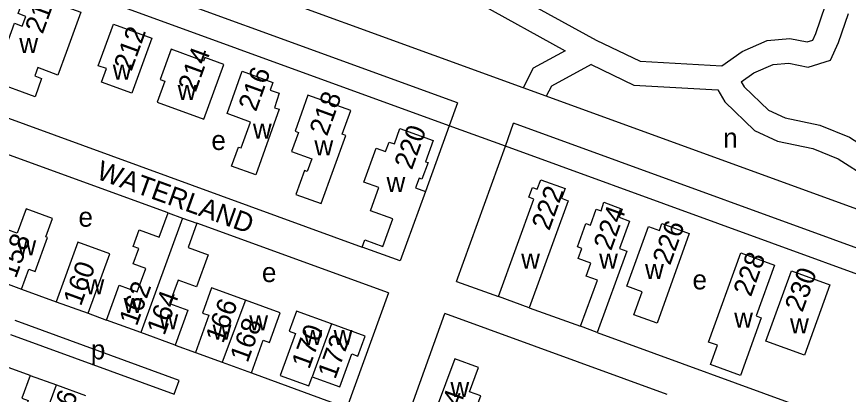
# Model space of a CAD drawing. Extents: x 154320 to 156262, y 382651 to 384180.
# Drawn here: x 155813.5 to 155984.2, y 382955.7 to 383033.1 of the extents above; entities that cross this region are included whole.
import ezdxf

# ---------------------------------------------------------------- set-up
doc = ezdxf.new("R2010")
doc.units = 0
for name, color, linetype in [('BLT_Basislijn', 7, 'Continuous'), ('BLT_Bebouwing', 7, 'Continuous'), ('BLT_Centroide', 7, 'Continuous'), ('BLT_Huisnummer', 7, 'Continuous'), ('BLT_Onderverdeling_panden', 7, 'Continuous'), ('BLT_Straatnaam', 7, 'Continuous'), ('BLT_Vlakafsluiter', 7, 'Continuous')]:
    doc.layers.add(name, color=color, linetype=linetype)

msp = doc.modelspace()

# ---------------------------------------------------------------- linework, layer by layer
at = {"layer": 'BLT_Basislijn'}
for p, q in [((155922.18, 383016.83), (155917.44, 383018.56)), ((156004.18, 382987.02), (155922.18, 383016.83)), ((155903.98, 383015.47), (155902.27, 383010.77)), ((155805.26, 383014.66), (155884.39, 382985.88)), ((155902.27, 383010.77), (155897.36, 382997.29)), ((155913.78, 383006.59), (155915.48, 383011.29)), ((155903.75, 382978.84), (155913.78, 383006.59)), ((155844.57, 382992.89), (155811.27, 383005.01)), ((155889.8, 382976.47), (155850.46, 382990.76)), ((155903.75, 382978.84), (155912.34, 382975.73)), ((155814.49, 382977.24), (155821.58, 382974.65)), ((155889.8, 382976.47), (155881.23, 382952.91)), ((155918.67, 382973.44), (155929.23, 382969.64)), ((155846.86, 382958.56), (155813.21, 382970.8)), ((155828.14, 382972.3), (155831.93, 382970.92)), ((155893.06, 382949.27), (155901.37, 382972.26)), ((155946.99, 382955.63), (155901.37, 382972.26)), ((155812.2, 382967.97), (155845.84, 382955.74)), ((155932.61, 382968.4), (155990.87, 382947.17)), ((155846.05, 382965.8), (155850.16, 382964.28)), ((155816.27, 382959.55), (155821.65, 382957.62)), ((155861.67, 382960.11), (155881.23, 382952.91))]:
    msp.add_line(p, q, dxfattribs=at)
for points in [[(155853.65, 383062.66), (155866.44, 383057.77), (155872.53, 383054.76), (155877.48, 383050.43), (155881.4, 383046.27), (155884.9, 383044.3), (155889.57, 383042.9), (155896.23, 383042.16), (155904.77, 383041.94), (155910.34, 383040.46), (155932.43, 383028.32)], [(155852.58, 383057.9), (155864.43, 383053.19), (155869.73, 383050.56), (155874.01, 383046.82), (155878.28, 383042.3), (155882.92, 383039.67), (155888.57, 383037.98), (155895.89, 383037.17), (155904.05, 383036.95), (155908.47, 383035.79), (155926.08, 383026.11), (155919.49, 383022.53), (155917.44, 383018.56)], [(155903.98, 383015.47), (155817.04, 383047.08)], [(155917.44, 383018.56), (155843.64, 383045.39)], [(155902.27, 383010.77), (155815.34, 383042.38)], [(155932.43, 383028.32), (155941.43, 383024.01), (155958.17, 383023.07), (155962.36, 383025.98), (155967.49, 383028.21), (155972.18, 383028.67), (155975.7, 383027.95), (155976.87, 383028.3), (155977.49, 383029.67), (155979.47, 383035.48)], [(155962.2, 383019.78), (155964.8, 383021.59), (155968.76, 383023.31), (155971.92, 383023.62), (155975.94, 383022.79), (155980.5, 383024.18), (155982.14, 383027.83), (155984.17, 383033.77)], [(155931.36, 383023.29), (155923.23, 383018.87), (155922.18, 383016.83)], [(155931.36, 383023.29), (155940.16, 383019.07), (155957.4, 383018.1)], [(155962.2, 383019.78), (155962.79, 383018.76), (155967.76, 383013.94), (155971.18, 383012.38), (155978.33, 383010.87), (155984.39, 383008.44), (155990.48, 383004.53), (155997.96, 383001.96), (156005.52, 383000.44), (156011.25, 382996.8)], [(155957.4, 383018.1), (155958.81, 383015.65), (155964.9, 383009.76), (155969.6, 383007.6), (155976.88, 383006.06), (155982.09, 383003.98), (155988.29, 383000), (155996.65, 382997.12), (156003.63, 382995.72), (156007.06, 382993.56), (156004.18, 382987.02)], [(156002.66, 382979.59), (155915.48, 383011.29)], [(156000.95, 382974.89), (155913.78, 383006.59)], [(155845.84, 382955.74), (155846.86, 382958.56)]]:
    msp.add_lwpolyline(points, dxfattribs=at)
at = {"layer": 'BLT_Bebouwing'}
for p, q in [((155844.57, 382992.89), (155847.5, 382991.83)), ((155847.5, 382991.83), (155850.46, 382990.76)), ((155808.04, 382979.61), (155814.49, 382977.24)), ((155918.67, 382973.44), (155912.34, 382975.73)), ((155932.61, 382968.4), (155929.23, 382969.64))]:
    msp.add_line(p, q, dxfattribs=at)
for points in [[(155815.34, 383038.14), (155826.66, 383034.03), (155823.68, 383025.81), (155821.96, 383021.11), (155817.81, 383022.67), (155817.2, 383020.97), (155818.61, 383020.47), (155817.26, 383016.69), (155808.67, 383019.81), (155813.04, 383031.76), (155814.64, 383031.16), (155815.37, 383033.18), (155813.77, 383033.75)], [(155833.36, 383031.61), (155841.21, 383028.73), (155837.13, 383017.47), (155830.92, 383019.72), (155831.93, 383022.47), (155830.25, 383023.07)], [(155845.22, 383026.44), (155842.97, 383020.26), (155843.91, 383019.91), (155842.33, 383015.58), (155851.91, 383012.09), (155856.01, 383023.32), (155852.1, 383024.76), (155851.84, 383024.03)], [(155859.79, 383021.94), (155866.04, 383019.63), (155865.51, 383018.04), (155867.38, 383017.42), (155866.4, 383014.46), (155867.37, 383014.13), (155862.54, 383000.7), (155857.58, 383002.49), (155858.99, 383006.4), (155859.58, 383006.2), (155861.49, 383011.5), (155856.68, 383013.25)], [(155873.27, 383017.02), (155870.64, 383009.65), (155871.33, 383009.4), (155869.9, 383005.47), (155874.04, 383003.97), (155873.11, 383001.38), (155872.54, 383001.58), (155870.78, 382996.66), (155875.99, 382994.8), (155881.02, 383008.75), (155880.31, 383009.04), (155882.06, 383013.88)], [(155945.91, 382990.69), (155951.5, 382988.68), (155944.91, 382970.29), (155940.17, 382972.02), (155941.88, 382976.71), (155938.69, 382977.88), (155943.14, 382990.07), (155945.39, 382989.25)], [(155962.08, 382984.71), (155969.04, 382982.18), (155965.25, 382971.77), (155966.3, 382971.39), (155962.01, 382959.57), (155955.85, 382961.82), (155957.3, 382965.75), (155955.46, 382966.42)], [(155972.47, 382980.98), (155980.39, 382978.13), (155975.16, 382963.7), (155967.26, 382966.56)]]:
    msp.add_lwpolyline(points, close=True, dxfattribs=at)
for points in [[(155884.73, 382999.21), (155887.29, 383006.19), (155889.21, 383005.48), (155889.92, 383007.42), (155891.01, 383007.03), (155892.13, 383010.16), (155898.98, 383007.7), (155897.41, 383003.39), (155897.94, 383003.2), (155896.66, 382999.78), (155896.07, 382999.98), (155895.34, 382998.02)], [(155912.34, 382975.73), (155919.61, 382995.73), (155918.59, 382996.11), (155919.34, 382998.13), (155920.34, 382997.76), (155921.04, 382999.65), (155926.04, 382997.87), (155925.32, 382995.88), (155926.68, 382995.39), (155918.67, 382973.44)], [(155884.39, 382985.88), (155884.93, 382987.37), (155888.61, 382986.03), (155890.66, 382991.65), (155886.07, 382993.31), (155886.85, 382995.46), (155887.81, 382998.11), (155884.73, 382999.21)], [(155895.34, 382998.02), (155897.36, 382997.29)], [(155897.36, 382997.29), (155892.19, 382983.05), (155884.39, 382985.88)], [(155929.23, 382969.64), (155932.68, 382979.09), (155930.38, 382979.95), (155931.29, 382982.61), (155928.75, 382983.53), (155929.5, 382985.6), (155928.56, 382985.93), (155930.28, 382990.72), (155931.28, 382990.36), (155932.43, 382993.64), (155933.42, 382993.28), (155933.99, 382995.06), (155937.76, 382993.68), (155937.14, 382991.99), (155939.23, 382991.22), (155937.17, 382985.57), (155938.68, 382985.02), (155932.61, 382968.4)], [(155814.49, 382977.24), (155815.98, 382981.38), (155817.31, 382980.89), (155819.85, 382987.84), (155819.48, 382987.97), (155820.85, 382991.73), (155815.41, 382993.72), (155813.59, 382988.73), (155811.62, 382989.45), (155808.04, 382979.61)], [(155831.93, 382970.92), (155834.53, 382978.05), (155838.25, 382976.69), (155840.02, 382981.51), (155837.39, 382982.47), (155838.54, 382985.6), (155837.42, 382986.01), (155838.66, 382989.39), (155842.76, 382987.92), (155844.57, 382992.89)], [(155850.46, 382990.76), (155848.67, 382985.78), (155852.77, 382984.3), (155850.38, 382977.75), (155846.62, 382979.12), (155844.88, 382974.31), (155848.64, 382972.95), (155846.05, 382965.8), (155846.05, 382965.8)], [(155828.14, 382972.3), (155832.59, 382984.5), (155826.01, 382986.88), (155821.58, 382974.65)], [(155860.45, 382974.97), (155853.47, 382977.5), (155851.64, 382972.35), (155852.91, 382971.89), (155850.16, 382964.28)], [(155821.58, 382974.65), (155828.14, 382972.3)], [(155861.67, 382960.11), (155864.1, 382966.79), (155865.39, 382966.35), (155867.58, 382972.37), (155860.45, 382974.97)], [(155878.07, 382970.16), (155870.91, 382972.76), (155869.43, 382968.64), (155870.72, 382968.18), (155867.58, 382959.53), (155873.45, 382957.4), (155874.13, 382959.29)], [(155838.99, 382968.36), (155831.93, 382970.92)], [(155874.13, 382959.29), (155879.8, 382957.22), (155882.24, 382963.97), (155883.53, 382963.53), (155885.01, 382967.65), (155878.07, 382970.16)], [(155846.05, 382965.8), (155838.99, 382968.36)], [(155850.16, 382964.28), (155855.68, 382962.28)], [(155855.68, 382962.28), (155861.67, 382960.11)], [(155902.55, 382945.75), (155904.08, 382949.87), (155906.38, 382949.01), (155908.73, 382955.38), (155906.4, 382956.2), (155908.29, 382961.2), (155903.41, 382963), (155897.67, 382947.56)], [(155816.27, 382959.55), (155810.47, 382961.69)], [(155816.27, 382959.55), (155814.55, 382954.88), (155815.83, 382954.41), (155813, 382946.72)], [(155822.86, 382942.78), (155822.31, 382941.32), (155822.02, 382941.43), (155823.03, 382944.26), (155817.52, 382946.27), (155821.65, 382957.62)], [(155821.65, 382957.62), (155827.65, 382955.46)]]:
    msp.add_lwpolyline(points, dxfattribs=at)
at = {"layer": 'BLT_Onderverdeling_panden'}
for p, q in [((155847.5, 382991.83), (155838.99, 382968.36)), ((155860.45, 382974.97), (155855.68, 382962.28)), ((155878.07, 382970.16), (155874.13, 382959.29))]:
    msp.add_line(p, q, dxfattribs=at)
at = {"layer": 'BLT_Vlakafsluiter'}
msp.add_line((155913.78, 383006.59), (155902.27, 383010.77), dxfattribs=at)

# ---------------------------------------------------------------- texts
at = {"layer": 'BLT_Centroide'}
for s, p in [('w', (155814.03, 383025.65)), ('w', (155833.21, 383020.2)), ('w', (155846.52, 383016.07)), ('w', (155861.97, 383008.14)), ('n', (155958.48, 383006.27)), ('w', (155874.59, 383004.69)), ('w', (155889.39, 382997.19)), ('w', (155813.63, 382984.2)), ('w', (155917.02, 382981.49)), ('w', (155933.02, 382981.49)), ('w', (155942.44, 382979.33)), ('w', (155827.61, 382976.22)), ('w', (155835.43, 382972.4)), ('w', (155960.73, 382969.39)), ('w', (155842.77, 382969.01)), ('w', (155861.22, 382968.82)), ('w', (155972.2, 382968.2)), ('w', (155853.69, 382966.93)), ('w', (155872.33, 382965.8)), ('w', (155878.54, 382965.8)), ('w', (155902.5, 382955.17))]:
    msp.add_text(s, height=4, dxfattribs=at).set_placement(p)
for s, p in [('e', (155853.43, 383005.8)), ('e', (155826.16, 382990.07)), ('e', (155863.81, 382978.72)), ('e', (155952.17, 382977.22)), ('p', (155828.7, 382962.87))]:
    msp.add_text(s, height=4, rotation=359.5, dxfattribs=at).set_placement(p)
at = {"layer": 'BLT_Huisnummer'}
for s, rotation, p in [('210', 70.0191, (155818.82, 383029.41)), ('212', 70.0191, (155837.05, 383021.77)), ('214', 70.0191, (155850.23, 383017.48)), ('216', 70.0191, (155862.6, 383013.48)), ('218', 70.0191, (155877.18, 383008.46)), ('220', 70.0191, (155894.59, 383001.55)), ('222', 70.0177, (155922.78, 382989.08)), ('224', 70.0177, (155935.48, 382984.98)), ('226', 70.0177, (155947.58, 382982)), ('158', 70.0179, (155813.34, 382979.31)), ('228', 70.0177, (155964.17, 382975.53)), ('160', 70.0179, (155826.66, 382973.61)), ('230', 70.0177, (155974.73, 382972.35)), ('162', 70.0179, (155838.13, 382969.52)), ('164', 70.0179, (155843.8, 382967.6)), ('166', 70.0179, (155855.85, 382965.97)), ('168', 70.0179, (155860.87, 382962.01)), ('170', 70.0179, (155873.51, 382960.68)), ('172', 70.0179, (155878.86, 382958.62)), ('86', 70.0179, (155824.07, 382950.07)), ('174', 70.0179, (155902.44, 382947.32))]:
    msp.add_text(s, height=4, rotation=rotation, dxfattribs=at).set_placement(p)
at = {"layer": 'BLT_Straatnaam'}
msp.add_text('WATERLAND', height=4, rotation=340.1818, dxfattribs=at).set_placement((155829.63, 382999.96))

doc.saveas('drawing.dxf')
